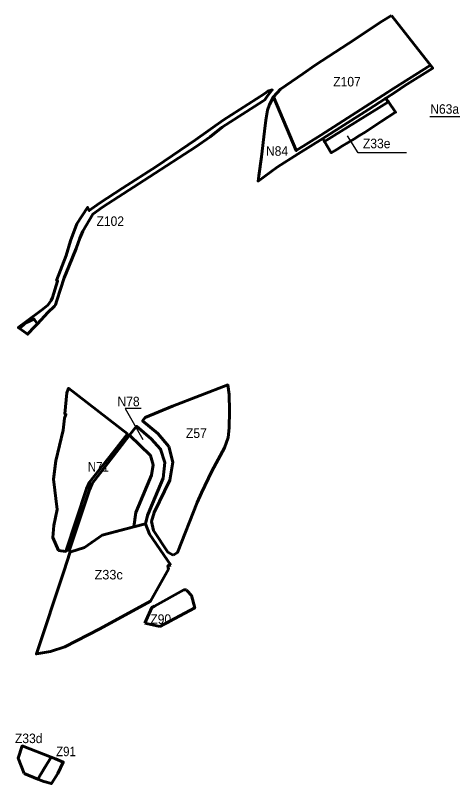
# Model space of a CAD drawing. Extents: x -650277 to -643425, y -1073980 to -1066720.
# Drawn here: x -648572 to -647467, y -1073980 to -1072042 of the extents above; entities that cross this region are included whole.
import ezdxf

# ---------------------------------------------------------------- set-up
doc = ezdxf.new("R2010")
doc.units = 0
doc.header["$LTSCALE"] = 9.6
for name, color, linetype, lineweight in [('15', 7, 'Continuous', 60), ('24', 7, 'Continuous', 60), ('34', 7, 'Continuous', 60), ('42', 7, 'Continuous', 60), ('45', 7, 'Continuous', 60), ('48', 7, 'Continuous', 60), ('5', 7, 'Continuous', 60), ('60', 7, 'Continuous', 60), ('63', 7, 'Continuous', 25), ('8', 7, 'Continuous', 60), ('9', 7, 'Continuous', 60)]:
    doc.layers.add(name, color=color, linetype=linetype, lineweight=lineweight)

msp = doc.modelspace()

# ---------------------------------------------------------------- linework, layer by layer
at = {"layer": '15'}
msp.add_lwpolyline([(-647795.4, -1072352.415), (-647679.66, -1072279.15), (-647637.082, -1072251.377), (-647629.67, -1072259.82), (-647791.198, -1072360.119)], close=True, dxfattribs=at)
at = {"layer": '24'}
for points in [[(-648524.04, -1072809.71), (-648525.08, -1072808.24), (-648547.06, -1072818.59), (-648561.69, -1072831.54), (-648554.22, -1072836.89), (-648541.102, -1072846.281), (-648522.66, -1072826.92), (-648516.44, -1072820.39)], [(-648549.76, -1073954.86), (-648515.333, -1073968.584), (-648498, -1073940), (-648481.749, -1073913.76), (-648554.42, -1073885.092), (-648564.75, -1073915.91)]]:
    msp.add_lwpolyline(points, close=True, dxfattribs=at)
at = {"layer": '34'}
for points in [[(-647621.97, -1072041.73), (-647649.76, -1072059.06), (-647683.63, -1072081.94), (-647730.53, -1072112.84), (-647814.58, -1072167.67), (-647845.58, -1072188.94), (-647901.91, -1072227.6), (-647919.68, -1072247.09), (-647862.615, -1072383.084)], [(-647523.71, -1072167.071), (-647545.44, -1072139.35), (-647621.97, -1072041.73)], [(-647862.615, -1072383.084), (-647800.2, -1072343.615), (-647642.504, -1072242.974), (-647616.719, -1072226.154), (-647523.71, -1072167.071)]]:
    msp.add_lwpolyline(points, dxfattribs=at)
at = {"layer": '42'}
for points in [[(-647637.082, -1072251.377), (-647611.306, -1072234.563), (-647589.02, -1072219.66), (-647517.51, -1072174.98), (-647523.71, -1072167.071), (-647616.719, -1072226.154), (-647642.504, -1072242.974), (-647800.2, -1072343.615)], [(-647800.2, -1072343.615), (-647862.615, -1072383.084), (-647919.68, -1072247.09), (-647930.36, -1072266.38), (-647934.86, -1072280.99), (-647939.26, -1072306.1), (-647942.54, -1072333.82), (-647950.2, -1072398.61), (-647956.786, -1072446.511), (-647958.82, -1072459.74), (-647910.27, -1072424.51), (-647857.52, -1072391.14), (-647795.4, -1072352.415)], [(-647795.4, -1072352.415), (-647679.66, -1072279.15), (-647637.082, -1072251.377)]]:
    msp.add_lwpolyline(points, dxfattribs=at)
at = {"layer": '45'}
for points in [[(-648463.25, -1073392.125), (-648444.523, -1073394.235), (-648392.43, -1073235.98), (-648384.6, -1073219.54), (-648315.955, -1073131.889), (-648289.148, -1073097.66), (-648437.643, -1072982.601), (-648442.187, -1072994.5), (-648447.043, -1073046.967), (-648444.11, -1073048.69), (-648448.1, -1073058.393)], [(-648448.1, -1073058.393), (-648450.875, -1073088.375), (-648469.875, -1073165.5), (-648475.437, -1073212.375), (-648466.687, -1073288.25), (-648474.5, -1073328.75), (-648477.562, -1073358.875), (-648463.25, -1073392.125)], [(-648272.642, -1073332.558), (-648268, -1073296), (-648261, -1073280), (-648228, -1073202), (-648224, -1073176), (-648231, -1073152), (-648283.884, -1073101.15), (-648311.798, -1073137.127), (-648378.17, -1073222.67), (-648385.09, -1073238.58), (-648436.857, -1073395.099)], [(-648397.062, -1073384.375), (-648378.125, -1073370.875), (-648352.312, -1073353), (-648314.687, -1073343.25), (-648272.642, -1073332.558)], [(-648436.857, -1073395.099), (-648432.187, -1073395.625), (-648397.062, -1073384.375)]]:
    msp.add_lwpolyline(points, dxfattribs=at)
at = {"layer": '48'}
msp.add_lwpolyline([(-648231, -1073152), (-648224, -1073176), (-648228, -1073202), (-648261, -1073280), (-648268, -1073296), (-648272.642, -1073332.558), (-648243.08, -1073325.04), (-648237.98, -1073303.4), (-648232.64, -1073289.31), (-648198.7, -1073209.08), (-648194.2, -1073170.13), (-648205.04, -1073136.07), (-648228.91, -1073110.54), (-648266.38, -1073078.59), (-648283.884, -1073101.15)], close=True, dxfattribs=at)
at = {"layer": '5'}
for points in [[(-648272.642, -1073332.558), (-648352.312, -1073353), (-648397.062, -1073384.375)], [(-648179.07, -1073428.81), (-648233.36, -1073350.68), (-648243.08, -1073325.04), (-648272.642, -1073332.558)], [(-648397.062, -1073384.375), (-648432.187, -1073395.625), (-648433.206, -1073395.51), (-648449.599, -1073445.278)], [(-648447.06, -1073635.39), (-648358.69, -1073589.35), (-648230.81, -1073520.18), (-648185.34, -1073438.91), (-648185.82, -1073435.12), (-648186.46, -1073430.01), (-648183.46, -1073429.52), (-648179.07, -1073428.81)], [(-648449.599, -1073445.278), (-648518.867, -1073652.836), (-648483.58, -1073646.7), (-648447.06, -1073635.39), (-648447.06, -1073635.39)]]:
    msp.add_lwpolyline(points, dxfattribs=at)
at = {"layer": '60'}
msp.add_line((-648245.341, -1073575.152), (-648207, -1073584), dxfattribs=at)
for points in [[(-648524.04, -1072809.71), (-648516.44, -1072820.39), (-648489.69, -1072791.37), (-648473.13, -1072775.58), (-648470.89, -1072772.42), (-648467.286, -1072761.426), (-648448.58, -1072704.37), (-648436.75, -1072675.79), (-648418.45, -1072629.91), (-648409.08, -1072604.25), (-648401.91, -1072586.1), (-648376.47, -1072543.52), (-648351.83, -1072525.81), (-648232.86, -1072449.45), (-648116.32, -1072373.44), (-648079.76, -1072348.46), (-648049.33, -1072323.77), (-647946.88, -1072257.82), (-647941.77, -1072254.45), (-647934.9, -1072244.55), (-647923.16, -1072229.85), (-647933.95, -1072233.18), (-647942.21, -1072238.54), (-648046.69, -1072306.3), (-648117.12, -1072356), (-648214.73, -1072422.41), (-648300.98, -1072478.1), (-648359.61, -1072515.85), (-648385.28, -1072534.41), (-648389.69, -1072526.36), (-648416.41, -1072567.43), (-648432.45, -1072610.56), (-648443.77, -1072648.02), (-648468.01, -1072710.44), (-648465.25, -1072712.03), (-648478.58, -1072753.49), (-648481.62, -1072761.39), (-648489.76, -1072772.74), (-648506.1, -1072785.56), (-648542.43, -1072812.6), (-648564.86, -1072829.45), (-648561.69, -1072831.54), (-648547.06, -1072818.59), (-648525.08, -1072808.24)], [(-648515.333, -1073968.584), (-648499.84, -1073974.76), (-648480.86, -1073980.25), (-648464.44, -1073954.69), (-648451.05, -1073925.87), (-648471, -1073918), (-648481.749, -1073913.76)]]:
    msp.add_lwpolyline(points, close=True, dxfattribs=at)
for points in [[(-648139.56, -1073491.4), (-648146.4, -1073491.55), (-648220.42, -1073532.43), (-648227.63, -1073535.89), (-648245.341, -1073575.152)], [(-648207, -1073584), (-648119, -1073537), (-648127.31, -1073505.75), (-648138.41, -1073493.62), (-648139.56, -1073491.4)]]:
    msp.add_lwpolyline(points, dxfattribs=at)
at = {"layer": '63'}
msp.add_line((-647525, -1072297), (-647387, -1072297), dxfattribs=at)
for points in [[(-647584, -1072389), (-647706, -1072389), (-647733, -1072346)], [(-648254, -1073034), (-648295, -1073034), (-648250, -1073112)]]:
    msp.add_lwpolyline(points, dxfattribs=at)
at = {"layer": '8'}
msp.add_lwpolyline([(-647629.67, -1072259.82), (-647611.51, -1072286.26), (-647648.09, -1072309.95), (-647688.26, -1072336.06), (-647702.35, -1072345.14), (-647716.62, -1072353.95), (-647730.97, -1072362.6), (-647745.32, -1072371.26), (-647759.68, -1072379.91), (-647774.04, -1072388.57), (-647791.198, -1072360.119)], close=True, dxfattribs=at)
at = {"layer": '9'}
for points in [[(-648030.86, -1073039.71), (-648032.09, -1072998.65), (-648035.592, -1072974.222), (-648175.061, -1073027.551), (-648244.214, -1073056.657), (-648250.491, -1073064.698), (-648212.22, -1073096.39), (-648184.37, -1073129.89)], [(-648101.67, -1073246.63), (-648075.34, -1073191.93), (-648043.29, -1073132.97), (-648034.43, -1073107.07), (-648031.8, -1073082.07), (-648030.86, -1073039.71)], [(-648184.37, -1073129.89), (-648174.03, -1073168.94), (-648182.12, -1073214.56), (-648221.39, -1073296.24), (-648227.75, -1073318.75), (-648223.03, -1073341.59), (-648186.47, -1073396.47), (-648173.38, -1073404.03)], [(-648173.38, -1073404.03), (-648162.55, -1073397.4), (-648112.36, -1073270.87), (-648101.67, -1073246.63)]]:
    msp.add_lwpolyline(points, dxfattribs=at)

# ---------------------------------------------------------------- texts
at = {"layer": '63'}
for s, width, p in [('Z107', 0.95, (-647769, -1072221)), ('N63a', 0.95, (-647524, -1072290)), ('Z33e', 0.95, (-647694, -1072377)), ('N84', 0.95, (-647939, -1072396)), ('Z102', 0.95, (-648367, -1072573)), ('N78', 0.95, (-648314, -1073028)), ('Z57', 0.95, (-648141, -1073108)), ('N71', 0.9, (-648389, -1073193)), ('Z90', 0.95, (-648231, -1073577)), ('Z33d', 0.95, (-648573, -1073878)), ('Z91', 0.9, (-648469, -1073911))]:
    msp.add_text(s, height=24, dxfattribs=dict(at, width=width)).set_placement(p)
msp.add_text('Z33c', height=24, dxfattribs=at).set_placement((-648372, -1073465))

doc.saveas('drawing.dxf')
